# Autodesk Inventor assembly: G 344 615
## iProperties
Company: Mayer & Müller AG Schaltgeräte
Created: 2005-10
Part Number: G 344 615
Document SubType Name: Schweißkonstruktion
Designer: I.Baliuc
Manufacturer: Standard
Standards Organization: Custom
Description: Schaltrohr, kompl.
Mass: 6799.6 g
Surface Area: 2913.7 cm^2
Volume: 865.277 cm^3
Density: 7.8583 g/cm^3
Zweck: Trenner 3 - polig
Author: T.Messerschmitt
Revision Number: 344615
